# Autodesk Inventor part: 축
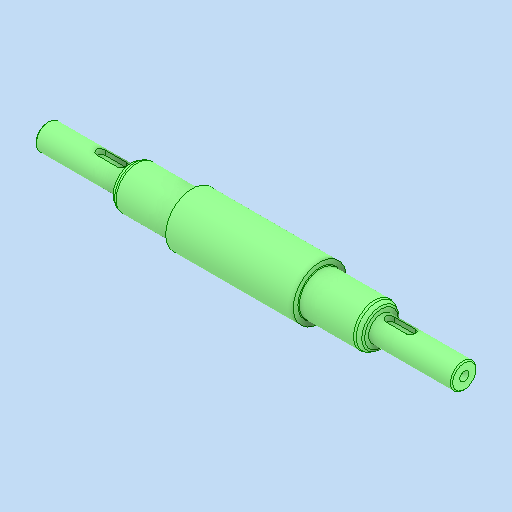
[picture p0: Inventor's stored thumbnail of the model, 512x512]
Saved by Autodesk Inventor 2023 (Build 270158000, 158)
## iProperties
Created: 2026-06
Part Number: 축
Material: 강철, 탄소
Document SubType Name: Modeling
Designer: home
Density: 7.85 g/cm^3
Appearance: 기본값
Sending System: Autodesk Inventor 2027
Preprocessor: ST-DEVELOPER v20.1
Author: jhkim
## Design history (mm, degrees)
feature "솔리드1"
node "솔리드2"
